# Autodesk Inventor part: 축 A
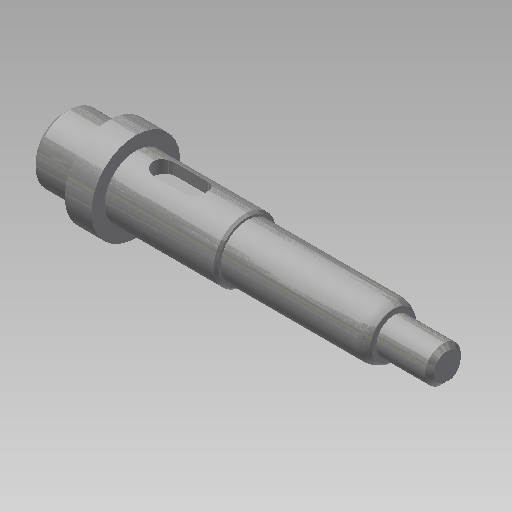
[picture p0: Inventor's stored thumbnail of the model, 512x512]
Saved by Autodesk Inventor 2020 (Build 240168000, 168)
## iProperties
Created: 2020-04
Part Number: 축 A
Material: 강철, 연강
Document SubType Name: Modeling
Designer: mduedu
Density: 7.86 g/cm^3
Mass: 91.1427 g
Surface Area: 41.2026 cm^2
Volume: 11.5958 cm^3
Appearance: 강철
Author: mduedu
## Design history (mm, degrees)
sketch "스케치1"
  geometry: L1 (0, 0)-(10, 0); L2 (10, 0)-(10, 7.5); L3 (10, 7.5)-(0, 7.5); L4 (0, 7.5)-(0, 0); L5 (10, 0)-(16, 0); L6 (16, 0)-(16, 10); L7 (16, 10)-(10, 10); L8 (10, 10)-(10, 0); L9 (16, 0)-(41, 0); L10 (41, 0)-(41, 7); L11 (41, 7)-(16, 7); L12 (16, 7)-(16, 0); L13 (41, 0)-(74, 0); L14 (74, 0)-(74, 6); L15 (74, 6)-(41, 6); L16 (41, 6)-(41, 0); L17 (74, 0)-(86, 0); L18 (86, 0)-(86, 4); L19 (86, 4)-(74, 4); L20 (74, 4)-(74, 0)
  constraints: 40 end point, 10 parallel, 5 horizontal, 5 perpendicular
  dimensions: "d0" = 86 distance between parallel lines of L18 L4; "d2" = 10 distance of L2.end L3.end; "d3" = 6 distance of L6.end L7.end; "d4" = 12 distance of L18.end L19.end; "d5" = 8 diameter of L19 L17; "d6" = 12 diameter of L15 L13; "d7" = 14 diameter of L11 L9; "d8" = 15 diameter of L3 L1; "d9" = 20 diameter of L7 L5; "d10" = 45 distance between parallel lines of L10 L18
revolve "회전1" sketch "스케치1" stored, may be unused: angle "d11" = 90 deg
sketch "스케치2"
  geometry: L1 (0, -7.5)-(0, 7.5) reference; L2 (0, 7.5)-(10, 7.5) reference; L3 (10, 7.5)-(10, 10) reference; L4 (10, 10)-(16, 10) reference; L5 (16, 10)-(16, 7) reference; L6 (16, 7)-(41, 7) reference; L7 (41, 7)-(41, 6) reference; L8 (41, 6)-(74, 6) reference; L9 (74, 6)-(74, 4) reference; L10 (74, 4)-(86, 4) reference; L11 (86, 4)-(86, -4) reference; L12 (86, -4)-(74, -4) reference; L13 (74, -4)-(74, -6) reference; L14 (74, -6)-(41, -6) reference; L15 (41, -6)-(41, -7) reference; L16 (41, -7)-(16, -7) reference; L17 (16, -7)-(16, -10) reference; L18 (16, -10)-(10, -10) reference; L19 (10, -10)-(10, -7.5) reference; L20 (10, -7.5)-(0, -7.5) reference; L21 (86, -4)-(78, -4); L22 (78, -4)-(78, -2.8); L23 (78, -2.8)-(86, -2.8); L24 (86, -2.8)-(86, -4); 1 further point
  constraints: 8 end point, 2 parallel, 1 horizontal, 1 perpendicular
  dimensions: "d12" = 8 distance of L22.end L23.end; "d13" = 1.2 distance of L21.end L22.end
extrude "돌출1" cut sketch "스케치2" stored distance "d14" = 2; taper "d15" = 0 deg
fillet "모깎기1" dims "d16" = 1
sketch "스케치3"
  geometry: L1 (0, -7.5)-(0, 7.5) reference; L2 (0, 7.5)-(10, 7.5) reference; L3 (10, 7.5)-(10, 10) reference; L4 (10, 10)-(16, 10) reference; L5 (16, 10)-(16, 7) reference; L6 (16, 7)-(41, 7) reference; L7 (41, 7)-(41, 6) reference; L8 (41, 6)-(74, 6) reference; L9 (74, 6)-(74, 4) reference; L10 (74, 4)-(86, 4) reference; L11 (86, 4)-(86, -2.8) reference; L12 (86, -2.8)-(78, -2.8) reference; L13 (78, -2.8)-(78, -4) reference; L14 (78, -4)-(74, -4) reference; L15 (74, -4)-(74, -6) reference; L16 (74, -6)-(41, -6) reference; L17 (41, -6)-(41, -7) reference; L18 (41, -7)-(16, -7) reference; L19 (16, -7)-(16, -10) reference; L20 (16, -10)-(10, -10) reference; L21 (10, -10)-(10, -7.5) reference; L22 (10, -7.5)-(0, -7.5) reference; L23 (20, 7)-(32, 7); L24 (32, 7)-(32, 4); L25 (32, 4)-(20, 4); L26 (20, 4)-(20, 7); 1 further point
  constraints: 8 end point, 2 parallel, 1 horizontal, 1 perpendicular, 1 point on line
  dimensions: "d17" = 12 distance of L24.end L25.end; "d18" = 3 distance of L23.end L24.end; "d19" = 4 distance from line of L26 L4.end
extrude "돌출2" cut sketch "스케치3" stored distance "d20" = 5; taper "d21" = 0 deg
fillet "모깎기2" dims "d22" = 2.5
chamfer "모따기1" distance "d23" = 1; stored, may be unused: second distance "d24" = 2, angle "d25" = 45 deg
chamfer "모따기2" distance "d26" = 0.5; stored, may be unused: second distance "d27" = 2, angle "d28" = 45 deg
fillet "모깎기3" dims "d29" = 0.3
chamfer "모따기3" distance "d30" = 1.56; stored, may be unused: second distance "d31" = 2, angle "d32" = 30 deg
fillet "모깎기4" dims "d33" = 4, "d34" = 0.5
node "솔리드1"
node "절단 모서리 투영1"
node "절단 모서리 투영2"
